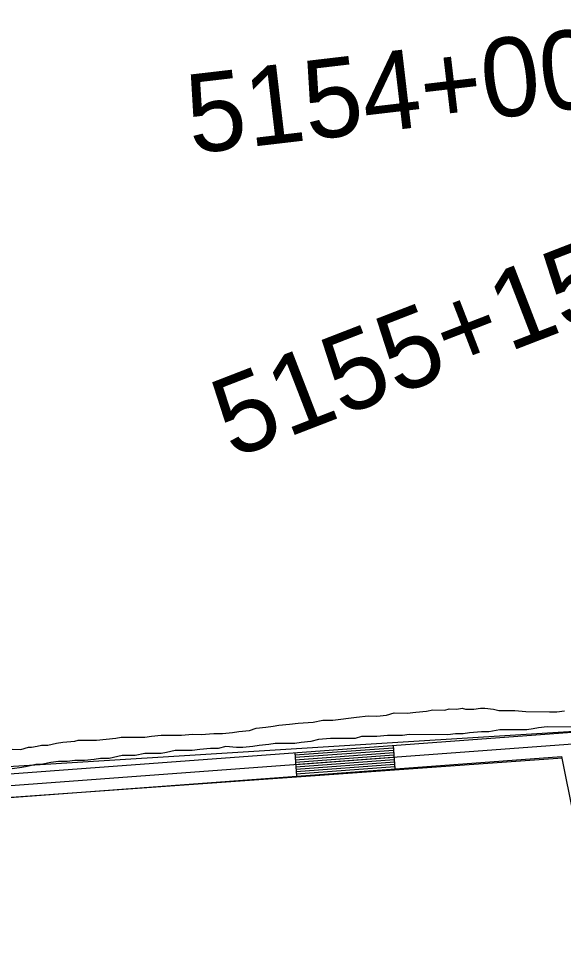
# Model space of a CAD drawing. Extents: x 3324125 to 3362000, y 600753 to 626151.
# Drawn here: x 3331027 to 3331718, y 620234 to 621408 of the extents above; entities that cross this region are included whole.
import ezdxf

# ---------------------------------------------------------------- set-up
doc = ezdxf.new("R2010")
doc.units = 0
for name, color, linetype in [('V-ROAD-CNTR', 7, 'Continuous'), ('V-SITE-VEGE', 7, 'Continuous'), ('V-SURV-IDEN', 7, 'Continuous'), ('V-TOPO-SHOR', 7, 'Continuous')]:
    doc.layers.add(name, color=color, linetype=linetype)

msp = doc.modelspace()

# ---------------------------------------------------------------- linework, layer by layer
at = {"layer": 'V-ROAD-CNTR'}
for p, q in [((3331502.3, 620486.4), (3331504.5, 620456.5)), ((3331377.6, 620477.2), (3331379.9, 620447.2))]:
    msp.add_line(p, q, dxfattribs=at)
for points in [[(3329012.5, 620307.8), (3330154.9, 620386.4), (3332441.5, 620556.1)], [(3328212.9, 620237.7), (3330156, 620371.5), (3332442.6, 620541.1)], [(3331377.9, 620474.2), (3331502.5, 620483.4)], [(3331378.1, 620471.2), (3331502.7, 620480.4)], [(3331378.3, 620468.2), (3331503, 620477.4)], [(3331378.5, 620465.2), (3331503.2, 620474.4)], [(3329859.2, 620336), (3330157.1, 620356.5), (3331715.9, 620472.2)], [(3331378.8, 620462.2), (3331503.4, 620471.4)], [(3331379, 620459.2), (3331503.6, 620468.5)], [(3331379.2, 620456.2), (3331503.9, 620465.5)], [(3331379.4, 620453.2), (3331504.1, 620462.5)], [(3331715.9, 620472.2), (3331776.9, 620167.5)], [(3331379.6, 620450.2), (3331504.3, 620459.5)]]:
    msp.add_lwpolyline(points, dxfattribs=at)
at = {"layer": 'V-SITE-VEGE'}
for points in [[(3331019.5, 620481.4), (3331030.4, 620481.3), (3331040, 620484), (3331044.1, 620483.9), (3331051, 620485.3), (3331056.4, 620486.6), (3331064.6, 620486.5), (3331075.6, 620489.2), (3331083.8, 620490.5), (3331098.8, 620491.8), (3331103, 620493.1), (3331126.2, 620493), (3331138.5, 620494.3), (3331150.8, 620495.6), (3331157.6, 620496.9), (3331187.7, 620496.7), (3331195.9, 620498), (3331208.2, 620499.3), (3331234.2, 620499.1), (3331247.9, 620500.4), (3331258.8, 620500.3), (3331275.2, 620501.6), (3331286.1, 620501.5), (3331298.5, 620502.8), (3331306.7, 620504.1), (3331320.3, 620505.4), (3331328.6, 620508.1), (3331340.9, 620509.4), (3331350.4, 620510.7), (3331357.3, 620512), (3331371, 620513.3), (3331381.9, 620514.6), (3331401, 620515.8), (3331413.4, 620518.5), (3331425.7, 620518.4), (3331455.8, 620522.3), (3331470.8, 620523.6), (3331481.7, 620523.5), (3331494, 620524.8), (3331503.6, 620527.4), (3331520, 620527.3), (3331531, 620528.6), (3331544.6, 620529.9), (3331552.8, 620531.2), (3331567.9, 620531.1), (3331573.4, 620532.5), (3331582.9, 620532.4), (3331589.8, 620533.7), (3331593.9, 620532.3), (3331604.8, 620532.3), (3331613, 620533.6), (3331618.5, 620533.5), (3331629.4, 620532.1), (3331636.2, 620530.7), (3331656.7, 620530.6), (3331670.4, 620529.1), (3331700.4, 620528.9), (3331704.5, 620528.9), (3331710, 620528.8), (3331719.6, 620530.1)], [(3331745.4, 620509.5), (3331697.6, 620509.8), (3331686.6, 620508.5), (3331679.8, 620507.2), (3331671.6, 620505.9), (3331651.1, 620506), (3331637.4, 620506.1), (3331623.7, 620503.4), (3331614.2, 620503.5), (3331599.1, 620502.2), (3331590.9, 620500.9), (3331581.4, 620501), (3331571.8, 620499.7), (3331522.6, 620500), (3331514.4, 620498.7), (3331495.2, 620498.8), (3331481.6, 620497.5), (3331462.4, 620497.6), (3331454.2, 620495), (3331422.8, 620495.2), (3331407.7, 620493.9), (3331398.2, 620491.2), (3331385.8, 620489.9), (3331377.6, 620488.6), (3331353, 620488.8), (3331344.8, 620487.5), (3331332.5, 620486.2), (3331324.3, 620484.9), (3331312, 620483.6), (3331303.8, 620483.6), (3331290.1, 620485.1), (3331280.6, 620482.4), (3331271, 620482.5), (3331257.3, 620481.2), (3331247.7, 620479.9), (3331225.9, 620480), (3331214.9, 620477.4), (3331208.1, 620476), (3331187.6, 620476.2), (3331175.3, 620473.5), (3331158.9, 620473.6), (3331142.4, 620469.6), (3331131.5, 620469.7), (3331123.3, 620468.4), (3331111, 620467.1), (3331098.7, 620467.2), (3331089.1, 620465.9), (3331078.2, 620466), (3331068.6, 620464.6), (3331056.3, 620462), (3331049.5, 620462), (3331038.5, 620459.4), (3331031.7, 620458.1), (3331019.4, 620456.8)]]:
    msp.add_lwpolyline(points, dxfattribs=at)
at = {"layer": 'V-TOPO-SHOR'}
for p, q in [((3330863, 620449.9), (3332003.3, 620521.5)), ((3329855.6, 620337.4), (3331716.9, 620470.4))]:
    msp.add_line(p, q, dxfattribs=at)

# ---------------------------------------------------------------- texts
at = {"layer": 'V-SURV-IDEN'}
for s, rotation, p in [('5154+00.4', 6.6961, (3331246.5, 621236.1)), ('5155+15.8', 21.1472, (3331298.7, 620849.3))]:
    msp.add_text(s, height=100, rotation=rotation, dxfattribs=at).set_placement(p)

doc.saveas('drawing.dxf')
